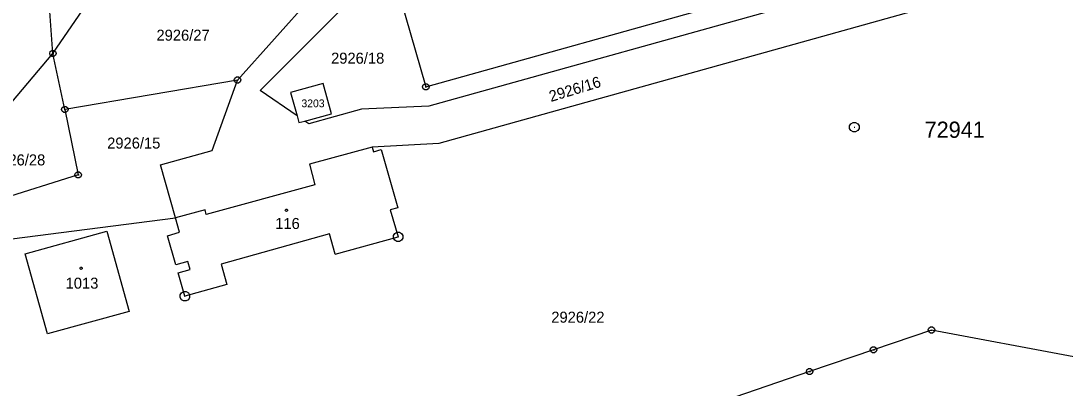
# Model space of a CAD drawing. Extents: x -760611 to -758411, y -1176479 to -1174807.
# Drawn here: x -758977.4 to -758816.2, y -1175101.5 to -1175044.9 of the extents above; entities that cross this region are included whole.
import ezdxf

# ---------------------------------------------------------------- set-up
doc = ezdxf.new("R2010")
doc.units = 0
for name, color, linetype in [('1', 7, 'Continuous'), ('11', 7, 'Continuous'), ('12', 7, 'Continuous'), ('2', 7, 'Continuous'), ('5', 7, 'Continuous'), ('8', 7, 'Continuous')]:
    doc.layers.add(name, color=color, linetype=linetype)

msp = doc.modelspace()

# ---------------------------------------------------------------- linework, layer by layer
at = {"layer": '1'}
for p, q in [((-758972.45, -1175049.88), (-758975.38, -1175010.24)), ((-758943.98, -1175053.98), (-758926.24, -1175034.18)), ((-758839.22, -1175037.05), (-758914.45, -1175058)), ((-758940.47, -1175055.61), (-758926.26, -1175041.33)), ((-758918.88, -1175041.24), (-758914.91, -1175055.04)), ((-758914.91, -1175055.04), (-758866.98, -1175041.66)), ((-758837.6, -1175042.81), (-758912.9, -1175063.8)), ((-758972.45, -1175049.88), (-758967.86, -1175043.13)), ((-758987.78, -1175067.99), (-758972.45, -1175049.88)), ((-758970.62, -1175058.53), (-758972.45, -1175049.88)), ((-758943.98, -1175053.98), (-758970.62, -1175058.53)), ((-758947.88, -1175064.85), (-758943.98, -1175053.98)), ((-758934.78, -1175059.5), (-758940.47, -1175055.61)), ((-758930.76, -1175054.54), (-758935.77, -1175055.92)), ((-758929.48, -1175059.2), (-758930.76, -1175054.54)), ((-758935.77, -1175055.92), (-758934.78, -1175059.5)), ((-758970.62, -1175058.53), (-758968.55, -1175068.63)), ((-758924.84, -1175058.48), (-758932.98, -1175060.73)), ((-758914.45, -1175058), (-758924.84, -1175058.48)), ((-758934.78, -1175059.5), (-758934.49, -1175060.55)), ((-758934.49, -1175060.55), (-758933.6, -1175060.31)), ((-758933.6, -1175060.31), (-758929.48, -1175059.2)), ((-758932.98, -1175060.73), (-758933.6, -1175060.31)), ((-758955.83, -1175067.05), (-758947.88, -1175064.85)), ((-758923.21, -1175064.32), (-758932.88, -1175066.95)), ((-758912.9, -1175063.8), (-758923.21, -1175064.32)), ((-758923.21, -1175064.32), (-758922.99, -1175065.06)), ((-758922.99, -1175065.06), (-758921.8, -1175064.71)), ((-758921.8, -1175064.71), (-758919.22, -1175073.69)), ((-758932.88, -1175066.95), (-758932.02, -1175070.13)), ((-758953.53, -1175075.25), (-758955.83, -1175067.05)), ((-758968.55, -1175068.63), (-758991.71, -1175075.87)), ((-758932.02, -1175070.13), (-758948.82, -1175074.75)), ((-758948.94, -1175074.02), (-758953.53, -1175075.25)), ((-758948.82, -1175074.75), (-758948.94, -1175074.02)), ((-758919.22, -1175073.69), (-758920.39, -1175074)), ((-758920.39, -1175074), (-758919.17, -1175078.17)), ((-758978.79, -1175078.51), (-758953.53, -1175075.25)), ((-758952.94, -1175077.47), (-758953.53, -1175075.25)), ((-758954.79, -1175078), (-758952.94, -1175077.47)), ((-758953.48, -1175082.51), (-758954.79, -1175078)), ((-758929.76, -1175077.73), (-758946.48, -1175082.38)), ((-758928.88, -1175080.88), (-758929.76, -1175077.73)), ((-758928.88, -1175080.88), (-758919.17, -1175078.17)), ((-758951.66, -1175081.98), (-758953.48, -1175082.51)), ((-758951.3, -1175083.21), (-758951.66, -1175081.98)), ((-758946.48, -1175082.38), (-758945.6, -1175085.53)), ((-758953.12, -1175083.74), (-758951.3, -1175083.21)), ((-758952.08, -1175087.34), (-758953.12, -1175083.74)), ((-758945.6, -1175085.53), (-758952.08, -1175087.34)), ((-758836.86, -1175092.56), (-758845.79, -1175095.61)), ((-758814.87, -1175096.72), (-758836.86, -1175092.56)), ((-758845.79, -1175095.61), (-758855.66, -1175098.98)), ((-758855.66, -1175098.98), (-758875.91, -1175105.89))]:
    msp.add_line(p, q, dxfattribs=at)
msp.add_lwpolyline([(-758976.75, -1175080.81), (-758964.16, -1175077.3), (-758960.7, -1175089.72), (-758973.31, -1175093.16)], close=True, dxfattribs=at)
at = {"layer": '12'}
for p, q in [((-758923.21, -1175064.32), (-758932.88, -1175066.95)), ((-758923.21, -1175064.32), (-758922.99, -1175065.06)), ((-758922.99, -1175065.06), (-758921.8, -1175064.71)), ((-758921.8, -1175064.71), (-758919.22, -1175073.69)), ((-758932.88, -1175066.95), (-758932.02, -1175070.13)), ((-758932.02, -1175070.13), (-758948.82, -1175074.75)), ((-758948.94, -1175074.02), (-758953.53, -1175075.25)), ((-758948.82, -1175074.75), (-758948.94, -1175074.02)), ((-758919.22, -1175073.69), (-758920.39, -1175074)), ((-758920.39, -1175074), (-758919.17, -1175078.17)), ((-758952.94, -1175077.47), (-758953.53, -1175075.25)), ((-758954.79, -1175078), (-758952.94, -1175077.47)), ((-758953.48, -1175082.51), (-758954.79, -1175078)), ((-758929.76, -1175077.73), (-758946.48, -1175082.38)), ((-758928.88, -1175080.88), (-758929.76, -1175077.73)), ((-758928.88, -1175080.88), (-758919.17, -1175078.17)), ((-758951.66, -1175081.98), (-758953.48, -1175082.51)), ((-758951.3, -1175083.21), (-758951.66, -1175081.98)), ((-758946.48, -1175082.38), (-758945.6, -1175085.53)), ((-758953.12, -1175083.74), (-758951.3, -1175083.21)), ((-758952.08, -1175087.34), (-758953.12, -1175083.74)), ((-758945.6, -1175085.53), (-758952.08, -1175087.34))]:
    msp.add_line(p, q, dxfattribs=at)
msp.add_lwpolyline([(-758976.75, -1175080.81), (-758964.16, -1175077.3), (-758960.7, -1175089.72), (-758973.31, -1175093.16)], close=True, dxfattribs=at)
at = {"layer": '5'}
for points in [[(-758936.42, -1175073.91), (-758936.32, -1175073.93), (-758936.27, -1175074.02), (-758936.25, -1175074.08), (-758936.27, -1175074.17), (-758936.35, -1175074.24), (-758936.42, -1175074.25), (-758936.51, -1175074.22), (-758936.57, -1175074.16), (-758936.59, -1175074.08), (-758936.57, -1175073.99), (-758936.49, -1175073.92)], [(-758968.11, -1175082.86), (-758968.01, -1175082.88), (-758967.96, -1175082.97), (-758967.94, -1175083.03), (-758967.96, -1175083.12), (-758968.04, -1175083.19), (-758968.11, -1175083.2), (-758968.2, -1175083.17), (-758968.26, -1175083.11), (-758968.28, -1175083.03), (-758968.26, -1175082.94), (-758968.18, -1175082.87)]]:
    msp.add_lwpolyline(points, close=True, dxfattribs=at)
at = {"layer": '8'}
for p, q in [((-758972.57, -1175049.88), (-758972.33, -1175049.88)), ((-758944.1, -1175053.98), (-758943.86, -1175053.98)), ((-758915.03, -1175055.04), (-758914.79, -1175055.04)), ((-758970.74, -1175058.53), (-758970.5, -1175058.53)), ((-758848.81, -1175061.25), (-758848.71, -1175061.25)), ((-758968.67, -1175068.63), (-758968.43, -1175068.63)), ((-758919.22, -1175078.17), (-758919.12, -1175078.17)), ((-758952.13, -1175087.34), (-758952.03, -1175087.34)), ((-758836.98, -1175092.56), (-758836.74, -1175092.56)), ((-758845.91, -1175095.61), (-758845.67, -1175095.61)), ((-758855.78, -1175098.98), (-758855.54, -1175098.98))]:
    msp.add_line(p, q, dxfattribs=at)
for points in [[(-758972.3, -1175049.4), (-758972.05, -1175049.58), (-758971.95, -1175049.87), (-758972.05, -1175050.16), (-758972.3, -1175050.34), (-758972.61, -1175050.34), (-758972.86, -1175050.16), (-758972.96, -1175049.87), (-758972.86, -1175049.58), (-758972.61, -1175049.4)], [(-758943.83, -1175053.5), (-758943.58, -1175053.68), (-758943.48, -1175053.97), (-758943.58, -1175054.26), (-758943.83, -1175054.44), (-758944.14, -1175054.44), (-758944.39, -1175054.26), (-758944.49, -1175053.97), (-758944.39, -1175053.68), (-758944.14, -1175053.5)], [(-758914.76, -1175054.56), (-758914.51, -1175054.74), (-758914.41, -1175055.03), (-758914.51, -1175055.32), (-758914.76, -1175055.5), (-758915.07, -1175055.5), (-758915.32, -1175055.32), (-758915.42, -1175055.03), (-758915.32, -1175054.74), (-758915.07, -1175054.56)], [(-758970.47, -1175058.05), (-758970.22, -1175058.23), (-758970.12, -1175058.52), (-758970.22, -1175058.81), (-758970.47, -1175058.99), (-758970.78, -1175058.99), (-758971.03, -1175058.81), (-758971.13, -1175058.52), (-758971.03, -1175058.23), (-758970.78, -1175058.05)], [(-758848.57, -1175060.53), (-758848.23, -1175060.72), (-758848.04, -1175061.06), (-758848.04, -1175061.45), (-758848.23, -1175061.79), (-758848.57, -1175061.98), (-758848.96, -1175061.98), (-758849.3, -1175061.79), (-758849.49, -1175061.45), (-758849.49, -1175061.06), (-758849.3, -1175060.72), (-758848.96, -1175060.53)], [(-758968.4, -1175068.15), (-758968.15, -1175068.33), (-758968.05, -1175068.62), (-758968.15, -1175068.91), (-758968.4, -1175069.09), (-758968.71, -1175069.09), (-758968.96, -1175068.91), (-758969.06, -1175068.62), (-758968.96, -1175068.33), (-758968.71, -1175068.15)], [(-758918.98, -1175077.45), (-758918.64, -1175077.64), (-758918.45, -1175077.98), (-758918.45, -1175078.37), (-758918.64, -1175078.71), (-758918.98, -1175078.9), (-758919.37, -1175078.9), (-758919.71, -1175078.71), (-758919.9, -1175078.37), (-758919.9, -1175077.98), (-758919.71, -1175077.64), (-758919.37, -1175077.45)], [(-758951.89, -1175086.62), (-758951.55, -1175086.81), (-758951.36, -1175087.15), (-758951.36, -1175087.54), (-758951.55, -1175087.88), (-758951.89, -1175088.07), (-758952.28, -1175088.07), (-758952.62, -1175087.88), (-758952.81, -1175087.54), (-758952.81, -1175087.15), (-758952.62, -1175086.81), (-758952.28, -1175086.62)], [(-758836.71, -1175092.08), (-758836.46, -1175092.26), (-758836.36, -1175092.55), (-758836.46, -1175092.84), (-758836.71, -1175093.02), (-758837.02, -1175093.02), (-758837.27, -1175092.84), (-758837.37, -1175092.55), (-758837.27, -1175092.26), (-758837.02, -1175092.08)], [(-758845.64, -1175095.13), (-758845.39, -1175095.31), (-758845.29, -1175095.6), (-758845.39, -1175095.89), (-758845.64, -1175096.07), (-758845.95, -1175096.07), (-758846.2, -1175095.89), (-758846.3, -1175095.6), (-758846.2, -1175095.31), (-758845.95, -1175095.13)], [(-758855.51, -1175098.5), (-758855.26, -1175098.68), (-758855.16, -1175098.97), (-758855.26, -1175099.26), (-758855.51, -1175099.44), (-758855.82, -1175099.44), (-758856.07, -1175099.26), (-758856.17, -1175098.97), (-758856.07, -1175098.68), (-758855.82, -1175098.5)]]:
    msp.add_lwpolyline(points, close=True, dxfattribs=at)

# ---------------------------------------------------------------- texts
at = {"layer": '11'}
msp.add_text('72941', height=2.5, dxfattribs=at).set_placement((-758837.92, -1175062.9))
at = {"layer": '2'}
for s, height, p in [('2926/27', 1.7, (-758956.48, -1175047.91)), ('2926/18', 1.7, (-758929.53, -1175051.46)), ('3203', 1.2, (-758934.1, -1175058.18)), ('2926/15', 1.7, (-758964.09, -1175064.56)), ('2926/28', 1.7, (-758981.86, -1175067.16)), ('116', 1.7, (-758938.15, -1175076.97)), ('1013', 1.7, (-758970.5, -1175086.18)), ('2926/22', 1.7, (-758895.54, -1175091.43))]:
    msp.add_text(s, height=height, dxfattribs=at).set_placement(p)
msp.add_text('2926/16', height=1.7, rotation=16.845, dxfattribs=at).set_placement((-758895.59, -1175057.37))

doc.saveas('drawing.dxf')
